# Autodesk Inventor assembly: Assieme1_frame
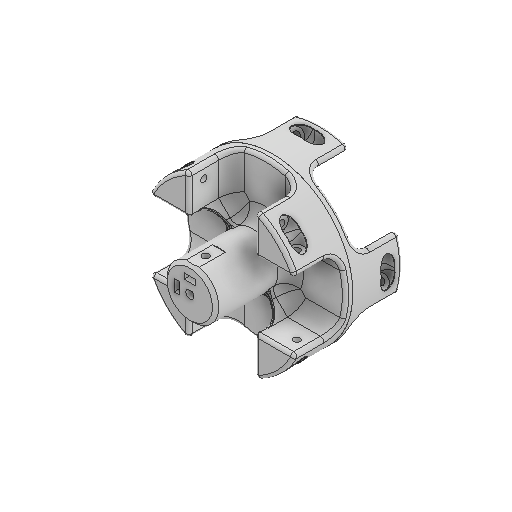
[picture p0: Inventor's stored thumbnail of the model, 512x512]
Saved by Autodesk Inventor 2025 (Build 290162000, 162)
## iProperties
Created: 2025-05
Part Number: Assieme1_frame
Document SubType Name: Assembly
Designer: R5800u
Author: R5800u
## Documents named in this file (3)
- C:\Users\R5800u\Desktop\mecanum7\Assieme1_frame.iam
- C:\Users\R5800u\Desktop\mecanum7\Parte1c.ipt
- C:\Users\R5800u\Desktop\mecanum7\Parte1a.ipt
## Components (2 placed, 2 different names)
1. Parte1c:1 — Coincidente:1, Coincidente:2, Angolo:1
2. Parte1a:1 — Coincidente:1, Coincidente:2, Angolo:1
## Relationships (3: Mate 2, Angle 1)
- Coincidente:1 [Mate]: Parte1c:1 ↔ Parte1a:1
- Coincidente:2 [Mate]: Parte1c:1 ↔ Parte1a:1
- Angolo:1 [Angle]: Parte1c:1 ↔ Parte1a:1
